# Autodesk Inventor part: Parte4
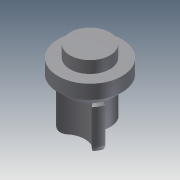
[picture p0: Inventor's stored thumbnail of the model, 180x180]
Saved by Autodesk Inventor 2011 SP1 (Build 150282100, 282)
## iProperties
Created: 2014-01
Part Number: Parte4
Document SubType Name: Modeling
Designer: UTENTE
Density: 1 g/cm^3
Author: UTENTE
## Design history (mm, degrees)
sketch "Schizzo1"
  geometry: C1 r 6 at (0, 0); 1 further point
  constraints: 1 centre point, 1 coincident
extrude "Estrusione1" new body sketch "Schizzo1" distance "d1" = 11; taper "d2" = 0 deg
chamfer "Smusso1" distance "d3" = 0.5; stored, may be unused: second distance "d4" = 2, angle "d5" = 45 deg
sketch "Schizzo2"
  geometry: C1 r 5.5 at (0, 0) reference; C2 r 8 at (0, 0)
  constraints: 1 centre point, 1 coincident
extrude "Estrusione2" join sketch "Schizzo2" distance "d7" = 6; taper "d8" = 0 deg
sketch "Schizzo3"
  geometry: C1 r 8 at (0, 0) reference; C2 r 5 at (0, 0)
  constraints: 1 centre point, 1 coincident
extrude "Estrusione3" join sketch "Schizzo3" distance "d10" = 3; taper "d11" = 0 deg
fillet "Raccordo1" dims "d12" = 2
sketch "Schizzo4"
  geometry: L1 (-5.5, 11)-(-8, 11) reference; L2 (-8, 11)-(-8, 17) reference; L3 (-8, 17)-(-5, 17) reference; L4 (-5, 17)-(-5, 20) reference; L5 (-5, 20)-(5, 20) reference; L6 (5, 20)-(5, 17) reference; L7 (5, 17)-(8, 17) reference; L8 (8, 17)-(8, 11) reference; L9 (8, 11)-(5.5, 11) reference; L10 (5.5, 11)-(6, 10.5) reference; L11 (6, 10.5)-(6, 2) reference; L12 (4, 0)-(-4, 0) reference; L13 (-6, 2)-(-6, 10.5) reference; L14 (-6, 10.5)-(-5.5, 11) reference; L15 (-5.5, 11)-(-10.468, 15.968); L16 (-10.468, 15.968)-(-10.468, 11); L17 (-10.468, 11)-(-5.5, 11); L18 (0, -4.497)-(0, 24.083) reference; A1 r 2 centre (4, 2) between (4, 0) and (6, 2) reference; A2 r 2 centre (-4, 2) between (-6, 2) and (-4, 0) reference; 1 further point
  constraints: 6 end point, 2 perpendicular, 1 parallel
revolve "Rivoluzione1" sketch "Schizzo4" stored, may be unused: angle "d13" = 90 deg
sketch "Schizzo5"
  geometry: C1 r 5 at (-5.441, 3.141); C2 r 5 at (0, -6.283); C3 r 5 at (5.441, 3.141); 1 further point
  constraints: 3 centre point, 7 other
  dimensions: "d25" = 360 deg dimension on point (0, 0) C1.centre (derived)
extrude "Estrusione4" cut sketch "Schizzo5" distance "d27" = 11; taper "d28" = 0 deg
node "Solido1"
node "Proietta spigoli di taglio1"
